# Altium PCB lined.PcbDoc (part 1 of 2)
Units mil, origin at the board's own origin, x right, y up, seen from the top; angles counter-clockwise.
Board outline 3500.17 x 4287.12 mil, 2 copper layers (Top Layer, Bottom Layer); 109 components, 117 nets, 494 pads, 325 vias.
Unrouted connection lines stored in the file: 3.
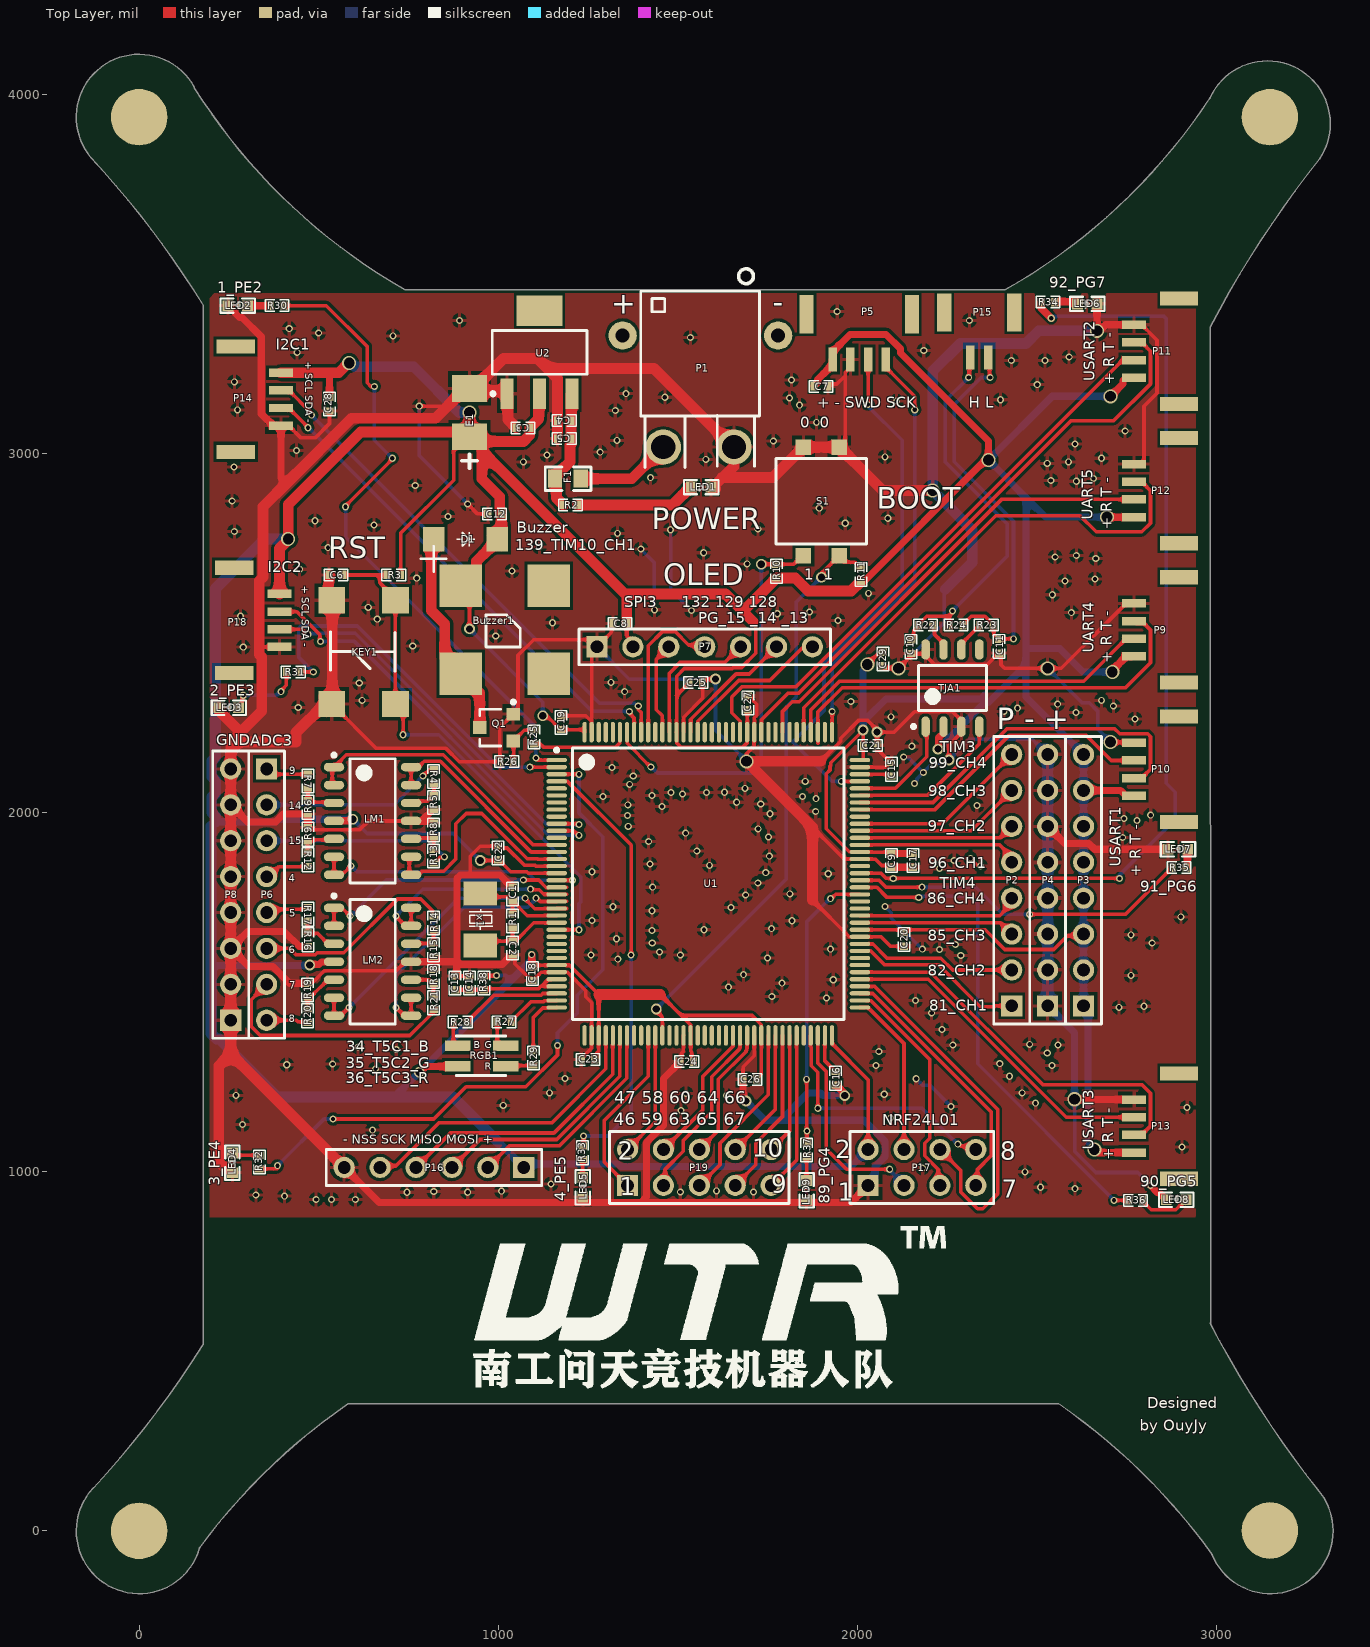
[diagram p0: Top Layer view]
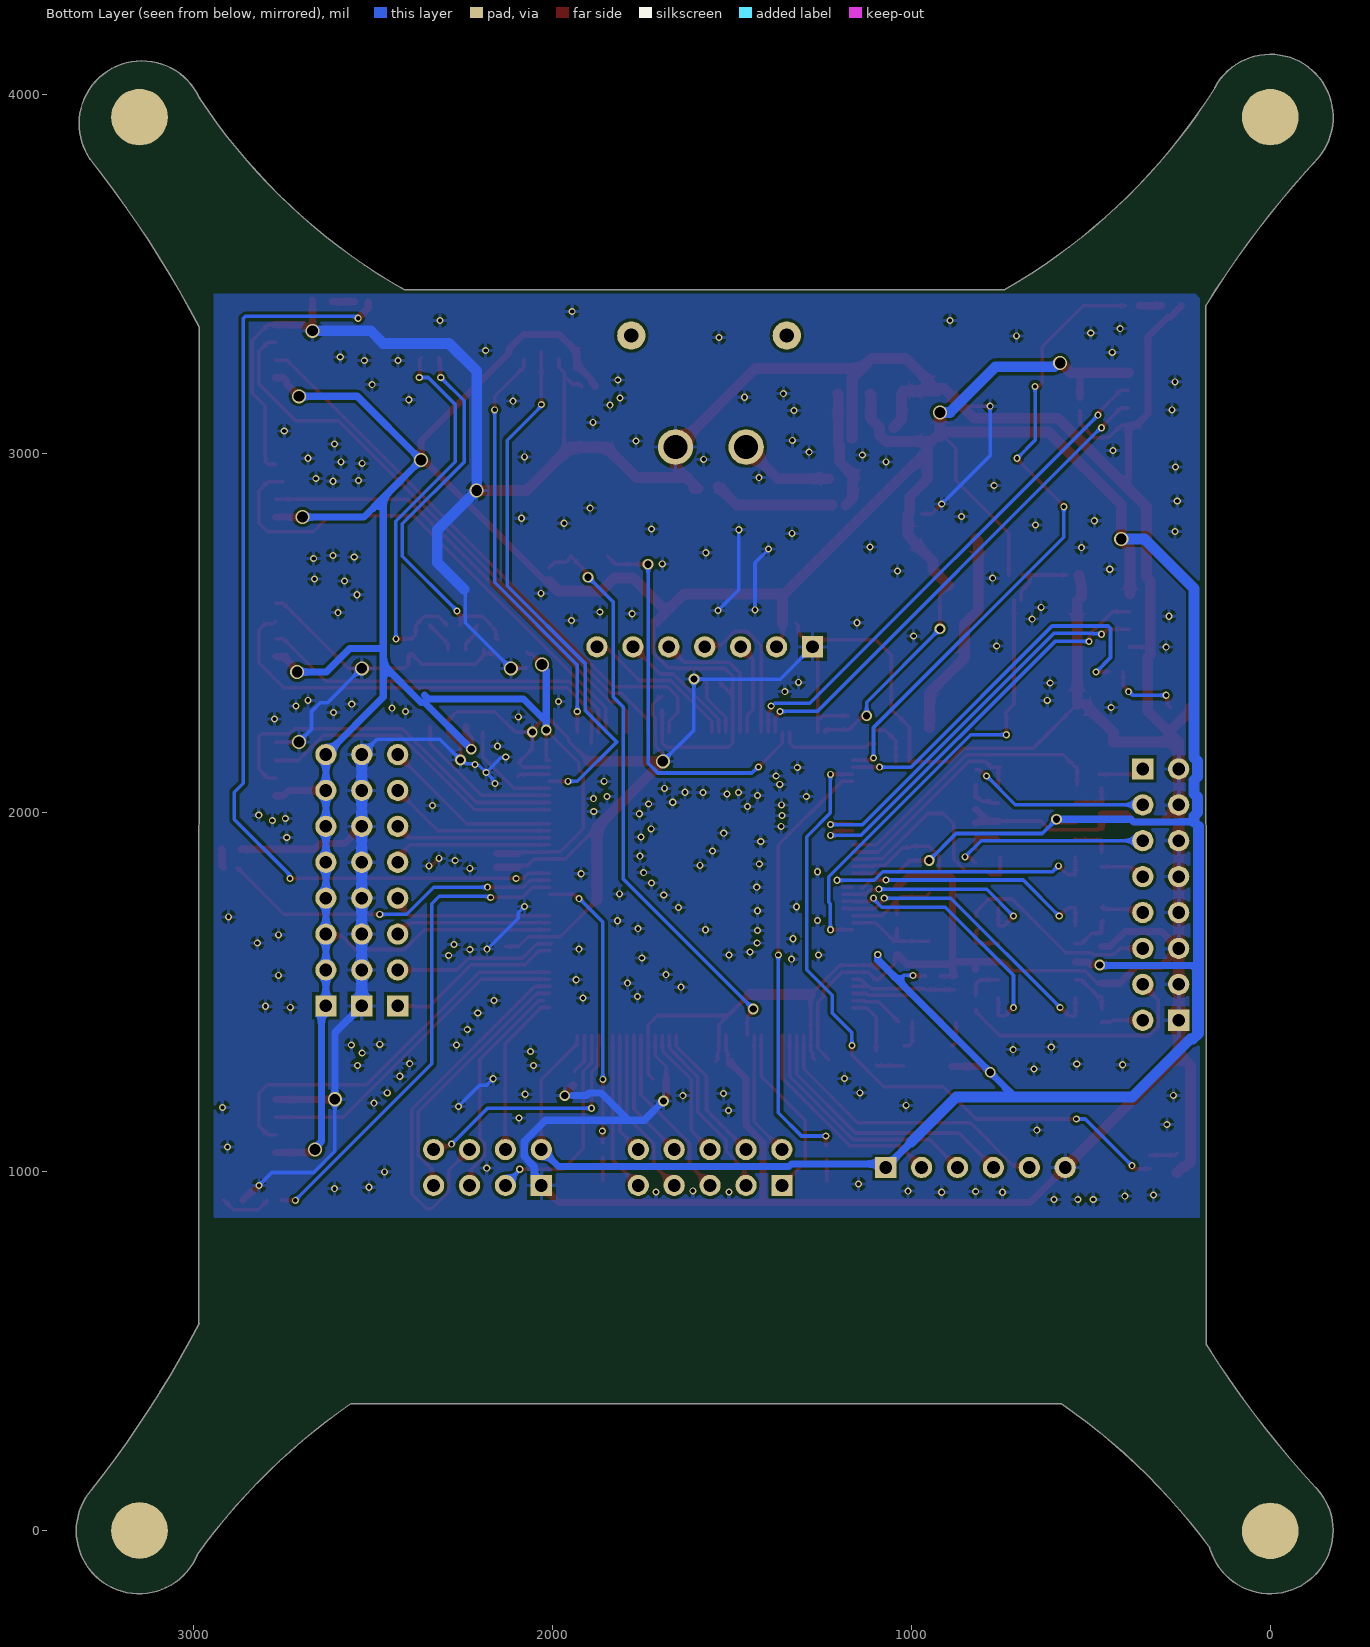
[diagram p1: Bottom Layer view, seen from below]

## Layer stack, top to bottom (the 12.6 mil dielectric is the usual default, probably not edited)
Top Solder: solder mask 0.4, Solder Resist, Dk 3.5
Top Layer: signal copper 1.4
Dielectric 1: dielectric 12.6, FR-4, Dk 4.8
Bottom Layer: signal copper 1.4
Bottom Solder: solder mask 0.4, Solder Resist, Dk 3.5

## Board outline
167.93,-49.57 ccw(c163.12,-48.15) 168.13,-48.15 ccw(c163.12,-48.15) 168.05,-47.24 cw(c1570.21,-1079.6) 581.36,353.58 ccw(c578.51,357.71) 581.98,354.09 ccw(c583,359) 583,353.98 2557.27,353.98 ccw(c2557.27,359) 2559.71,354.62 cw(c1564,-1088) 2987.16,-64.67 ccw(c2991.23,-61.74) 2987.79,-65.39 ccw(c2992.78,-64.85) 2988.14,-66.77 ccw(c3150,0) 3325.09,0 ccw(c3150,0) 3282.24,114.75 ccw(c3278.45,111.47) 3282.04,114.97 ccw(c3278,112) 3281.94,115.1 cw(c5634.72,1965.17) 2982.72,577.64 ccw(c2979,581) 2984.02,581 ccw(c2979,581) 2984.02,581 2982.38,3352.51 cw(c5629.85,1961.54) 3286.87,3820.13 ccw(c3282.94,3823.25) 3287.68,3821.59 ccw(c3284,3825) 3288.18,3822.23 ccw(c3142.11,3918.77) 3317.2,3918.77 ccw(c3142.11,3918.77) 2982.26,3990.2 ccw(c2985,3986) 2980.81,3988.76 cw(c1584.9,4910.46) 2411,3455.93 ccw(c2410.1,3451) 2410.1,3456.02 740.86,3456.02 ccw(c737.85,3452.01) 740.34,3456.36 cw(c1571.31,4910.32) 153.91,4018.42 ccw(c148.94,4019.11) 153.96,4019.11 ccw(c148.94,4019.11) 153.33,4021.53 ccw(c0,3937) -133.4,3823.6 ccw(c-129,3826) -132.69,3822.6 cw(c-2129,1980.08) 179.16,3412.76 177.98,520 ccw(c183,520) 178.16,518.68 ccw(c181.15,514.65) 176.9,517.32 cw(c-2129,1966) -127.15,119.8 ccw(c-125.1,115.22) -128.79,118.62 ccw(c0,0)

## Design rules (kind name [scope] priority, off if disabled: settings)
Clearance [All] p1: gap=8 ignorepadtopadclearanceinfootprint=TRUE except(0: Arc-Hole Track-Hole SMDPad-Hole THPad-Hole Via-Hole Fill-Hole Poly-Hole Region-Hole Text-Hole)
ComponentClearance [All] p1: gap=0 collisioncheckmode=3 verticalgap=0 showdistances=FALSE
MinimumSolderMaskSliver [All] p1: minsoldermaskwidth=0
PolygonConnect [All] p1: connectstyle=Relief reliefconductorwidth=10 reliefentries=4 polygonreliefangle="90 Angle" airgapwidth=10
RoutingVias [All] p1: holewidth=11.81 width=19.68 viastyle="Through Hole" minholewidth=11.81 minwidth=11.81 maxholewidth=39.37 maxwidth=39.37
SilkToSilkClearance [All] p1: silktosilkclearance=0
SilkToSolderMaskClearance [IsPad] p1: minsilkscreentomaskgap=0 clearancetoexposedcopper=TRUE
SolderMaskExpansion [All] p1: expansion=4
Width [All] p1: maxlimit=100 minlimit=5 preferedwidth=10
26 further rules are at their usual default settings.

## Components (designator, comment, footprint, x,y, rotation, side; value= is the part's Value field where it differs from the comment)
Buzzer1 "Buzzer" BUZZER 1185.3,2677 r180 top
C1 "22PF" 0402 1040,1773.5 r90 top
C2 "22PF" 0402 1040,1623.5 r270 top
C3 "0.1uf" 0402 1069,3072 r180 top
C4 "0.1uf" 0402 1184,3092 r180 top
C5 "10uf" 0402 1184,3042 r180 top
C6 "1uf" 0402 548,2662 r180 top
C7 "0.1uf" 0402 1899,3187 r180 top
C8 "0.1uf" 0402 1339,2527 r0 top
C9 "0.1uf" 0402 2095,1867 r270 top
C10 "30pf" 0402 2150,2462.4 r90 top
C11 "30pf" 0402 2395,2463.2 r90 top
C12 "10uf" 0402 990,2832.06 r0 top
C13 "10uf" 0402 880,1526 r270 top
C14 "104" 0402 920,1526 r270 top
C15 "225" 0402 2095,2121 r270 top
C16 "225" 0402 1939.77,1260.28 r90 top
C17 "106" 0402 2155,1867 r90 top
C18 "104" 0402 1095,1552 r90 top
C19 "104" 0402 1175,2251 r270 top
C20 "104" 0402 2130,1647 r90 top
C21 "104" 0402 2036,2187 r180 top
C22 "104" 0402 1000,1887.9 r270 top
C23 "104" 0402 1250,1312.7 r0 top
C24 "104" 0402 1525,1307 r0 top
C25 "104" 0402 1550,2362.24 r180 top
C26 "104" 0402 1701,1257.58 r0 top
C27 "104" 0402 1695,2305.61 r270 top
C28 "104" 0402 530,3138 r90 top
C29 "104" 0402 2070.89,2428 r90 top
D1 "DIODE" DIODE 997.17,2762 r180 top
E1 "100uF/10V" 3528 920,3047 r90 top
F1 "Fuse" 0805 1193.85,2930.15 r0 top
KEY1 "Key" 6*6*5轻触开关 625,2447 r90 top
LED1 "green" 0603 1565,2907 r0 top
LED2 "red" 0603 275,3412 r180 top
LED3 "red" 0603 250,2292 r180 top
LED4 "red" 0603 260,1025 r270 top
LED5 "red" 0603 1235.67,957 r270 top
LED6 "green" 0603 2640,3417 r0 top
LED7 "green" 0603 2893,1898.06 r180 top
LED8 "green" 0603 2887.98,922 r180 top
LED9 "green" 0603 1858.74,948.48 r270 top
LM1 "LM324" LM324 650,1977 r0 top
LM2 "LM324" LM324 650,1584.81 r0 top
P1 "Header 2" XT30-PW-M 1558,3215 r0 top
P2 "Header 8" HDR1X8 2430,1462 r90 top
P3 "Header 8" HDR1X8 2630,1462 r90 top
P4 "Header 8" HDR1X8 2530,1462 r90 top
P5 "Header 4" GH1.25_4P 2005.39,3341.72 r180 top
P6 "Header 8" HDR1X8 355,2122 r270 top
P7 "Header 7" HDR1X7 1275,2462 r0 top
P8 "Header 8" HDR1X8 255,1422 r90 top
P9 "Header 4" GH1.25_4P 2849.72,2508.89 r90 top
P10 "Header 4" GH1.25_4P 2849.72,2120.82 r90 top
P11 "Header 4" GH1.25_4P 2849.72,3285.03 r90 top
P12 "Header 4" GH1.25_4P 2849.72,2896.96 r90 top
P13 "Header 4" GH1.25_4P 2849.72,1127.39 r90 top
P14 "Header 4" GH1.25_4P 315.28,3151.61 r270 top
P15 "Header 2" GH1.25_2P 2437.05,3504.98 r180 top
P16 "Header 6" HDR1X6 1071,1012 r180 top
P17 "Header 4X2" HDR2X4 2030,962 r0 top
P18 "Header 4" GH1.25_4P 311.26,2535.35 r270 top
P19 "Header 5X2" HDR2X5 1360,962 r0 top
Q1 "S8050" SOT-23R 1000,2237 r90 top
R1 "1M" 0402 1040.13,1698.5 r90 top
R2 "560R" 0402 1201,2857 r0 top
R3 "10K" 0402 709,2662 r0 top
R4 "100K" 0402 820,2101 r270 top
R5 "100K" 0402 820,2028.06 r90 top
R6 "100K" 0402 469.97,2015 r90 top
R7 "100K" 0402 469.97,2088 r90 top
R8 "100K" 0402 820,1951.87 r270 top
R9 "100K" 0402 469.97,1940 r270 top
R10 "10K" 0402 1774.8,2672.64 r270 top
R11 "10K" 0402 2009.8,2663.64 r90 top
R12 "100K" 0402 469.97,1868.9 r270 top
R13 "100K" 0402 820,1879.06 r270 top
R14 "100K" 0402 820,1693 r270 top
R15 "100K" 0402 820,1618.16 r90 top
R16 "100K" 0402 469.97,1646 r90 top
R17 "100K" 0402 469.97,1717.19 r90 top
R18 "100K" 0402 820,1544.16 r270 top
R19 "100K" 0402 469.23,1506.16 r270 top
R20 "100K" 0402 469.23,1434.35 r270 top
R21 "100K" 0402 820,1471 r270 top
R22 "0R" 0402 2190,2522.2 r180 top
R23 "0R" 0402 2359,2522.2 r0 top
R24 "120R" 0402 2275,2522.2 r180 top
R25 "510R" 0402 1100,2211 r90 top
R26 "10K" 0402 1023.7,2142 r0 top
R27 "47R" 0402 1016.17,1417.55 r180 top
R28 "47R" 0402 894,1417 r0 top
R29 "68R" 0402 1097.58,1317 r270 top
R30 "1K" 0402 384,3412 r0 top
R31 "1K" 0402 429,2392 r0 top
R32 "1K" 0402 335,1027 r270 top
R33 "1K" 0402 1235,1053 r90 top
R34 "510R" 0402 2531,3422 r180 top
R35 "510R" 0402 2895.98,1847 r180 top
R36 "510R" 0402 2775,920.5 r180 top
R37 "510R" 0402 1858.68,1060.62 r90 top
R38 "10R" 0402 960,1526 r270 top
RGB1 "RGB" RGB_LED 954.14,1322 r0 top
S1 "Switch" SWITCH_2P 1899.8,2867.11 r0 top
TJA1 "TJA1050" TJA1050 2265,2347.2 r90 top
U1 "STM32F407ZGT6" STM32F103ZETx 1585,1802 r0 top
U2 "AMS1117-3.3" ASM1117 1115,3282 r90 top
x1 "8MHz" 8M晶振 950,1702.5 r270 top

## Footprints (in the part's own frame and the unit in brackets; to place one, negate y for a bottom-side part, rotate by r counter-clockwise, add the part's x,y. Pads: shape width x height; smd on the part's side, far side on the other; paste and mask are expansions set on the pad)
6*6*5轻触开关 [mm]
  rect 1.85x1.9 smd: 1(-3.675,2.25) 2(3.675,2.25) 3(-3.675,-2.25) 4(3.675,-2.25)
  silkscreen extent -1.35,-2.22 1.45,2.35
8M晶振 [mm]
  rect 1.7x2.4 smd: 1(-1.85,0) 2(1.85,0)
  silkscreen extent -0.72,-0.77 0.72,0.87, body extent -2.5,-1.6 2.5,1.6, height 0.25
0402 [mil]
  rect 20x23.62 smd: 1(-19,0) 2(19,0)
  silkscreen extent -33,-16 33,16
0603 [mil]
  rect 30x30 smd: 1(-27,0) 2(27.5,-0.06)
  silkscreen extent -48,-20 48,20
0805 [mil]
  rect 39.37x50 smd: 1(-36,0) 2(36,0)
  silkscreen extent -63,-33 64,33
3528 [mm]
  rect 1.9x2.5 smd: 1(0,0) 2(3.42,0)
  silkscreen extent -2.24,-0.56 -1.24,0.56
ASM1117 [mm] "SOT223, 4-Leads, Body 6.51x7.00mm (avg), Pitch 2.30mm, IPC Medium Density"
  rect 2.15x0.9 smd: 1(-2.93,2.3) 2(-2.93,0) 3(-2.93,-2.3)
  rect 2.15x3.25 smd: 4(2.93,0)
  silkscreen extent -3.05,-3.35 1.55,3.42, body extent -1.86,-3.35 1.86,3.35, height 1.8
BUZZER [mil]
  rect 118.11x118.11 smd: 1(290,45) 2(290,290) 3(45,290) 4(45,45)
  silkscreen extent 124,-65 400,216
DIODE [mm] "SODFL, 2-Leads, Body 3.63x5.35mm, IPC Medium Density"
  rect 1.52x1.724 smd: 1(0,0) 2(4.5,0)
  silkscreen extent 1.57,-0.5 2.86,0.52
GH1.25_2P [mm]
  rect 1x2.7 smd: 0(0,2.845) 0(4.95,2.845)
  rect 0.6x1.7 smd: 1(1.85,6.045) 2(3.1,6.045)
GH1.25_4P [mm]
  rect 1x2.7 smd: 0(-3.725,-1.175) 0(3.725,-1.175)
  rect 0.6x1.7 smd: 1(-1.875,2.025) 2(-0.625,2.025) 3(0.625,2.025) 4(1.875,2.025)
HDR1X6 [mm] "Connector; Header; 6 Position"
  rect 1.5x1.5 hole 0.9: 1(0,0)
  round 1.5 hole 0.9: 2(2.54,0) 3(5.08,0) 4(7.62,0) 5(10.16,0) 6(12.7,0)
  silkscreen extent -1.27,-1.27 13.97,1.27
HDR1X7 [mm] "Connector; Header; 7 Position"
  rect 1.5x1.5 hole 0.9: 1(0,0)
  round 1.5 hole 0.9: 2(2.54,0) 3(5.08,0) 4(7.62,0) 5(10.16,0) 6(12.7,0) 7(15.24,0)
  silkscreen extent -1.27,-1.27 16.51,1.27
HDR1X8 [mm] "Connector; Header; 8 Position"
  rect 1.5x1.5 hole 0.9: 1(0,0)
  round 1.5 hole 0.9: 2(2.54,0) 3(5.08,0) 4(7.62,0) 5(10.16,0) 6(12.7,0) 7(15.24,0) 8(17.78,0)
  silkscreen extent -1.27,-1.27 19.05,1.27
HDR2X4 [mm] "Connector; Header; 4x2 Position"
  rect 1.5x1.5 hole 0.9: 1(0,0)
  round 1.5 hole 0.9: 2(0,2.54) 3(2.54,0) 4(2.54,2.54) 5(5.08,0) 6(5.08,2.54) 7(7.62,0) 8(7.62,2.54)
  silkscreen extent -1.27,-1.27 8.89,3.81
HDR2X5 [mm] "Connector; Header; 5x2 Position"
  rect 1.5x1.5 hole 0.9: 1(0,0)
  round 1.5 hole 0.9: 2(0,2.54) 3(2.54,0) 4(2.54,2.54) 5(5.08,0) 6(5.08,2.54) 7(7.62,0) 8(7.62,2.54) 9(10.16,0) 10(10.16,2.54)
  silkscreen extent -1.27,-1.27 11.43,3.81
LM324 [mm] "SOIC, 14-Leads, Body 8.65x3.90mm, Pitch 1.27mm, IPC Medium Density"
  oval 1.45x0.6 smd: 1(-2.725,3.81) 2(-2.725,2.54) 3(-2.725,1.27) 4(-2.725,0) 5(-2.725,-1.27) 6(-2.725,-2.54) 7(-2.725,-3.81) 8(2.725,-3.81) 9(2.725,-2.54) 10(2.725,-1.27) 11(2.725,0) 12(2.725,1.27) 13(2.725,2.54) 14(2.725,3.81)
  silkscreen extent -2.85,-4.4 1.6,4.78, body extent -2,-4.4 2,4.4, height 1.75
RGB_LED [mm]
  rect 1.8x0.75 smd: 1(-1.7,-0.725) 2(-1.7,0.725) 3(1.7,-0.725) 4(1.7,0.725)
  silkscreen extent -1.8,-1.36 1.7,1.44
SOT-23R [mm] "SOT-23; 3 Leads; Body 3.0 x 2.5 mm, inc. leads (LxW max)"
  rect 0.9x0.95 smd: 1(0.95,-1.048) 2(-0.95,-1.048) 3(0,1.302)
  silkscreen extent -1.3,-1.19 1.93,1.3
STM32F103ZETx [mm] "TSQFP, 144-Leads, Body 20.00x20.00mm, Pitch 0.50mm, IPC Medium Density"
  oval 1.45x0.3 smd: 1(-10.725,8.75) 2(-10.725,8.25) 3(-10.725,7.75) 4(-10.725,7.25) 5(-10.725,6.75) 6(-10.725,6.25) 7(-10.725,5.75) 8(-10.725,5.25) 9(-10.725,4.75) 10(-10.725,4.25) 11(-10.725,3.75) 12(-10.725,3.25) 13(-10.725,2.75) 14(-10.725,2.25) 15(-10.725,1.75) 16(-10.725,1.25) 17(-10.725,0.75) 18(-10.725,0.25) 19(-10.725,-0.25) 20(-10.725,-0.75) 21(-10.725,-1.25) 22(-10.725,-1.75) 23(-10.725,-2.25) 24(-10.725,-2.75) 25(-10.725,-3.25) 26(-10.725,-3.75) 27(-10.725,-4.25) 28(-10.725,-4.75) 29(-10.725,-5.25) 30(-10.725,-5.75) 31(-10.725,-6.25) 32(-10.725,-6.75) 33(-10.725,-7.25) 34(-10.725,-7.75) 35(-10.725,-8.25) 36(-10.725,-8.75) 73(10.725,-8.75) 74(10.725,-8.25) 75(10.725,-7.75) 76(10.725,-7.25) 77(10.725,-6.75) 78(10.725,-6.25) 79(10.725,-5.75) 80(10.725,-5.25) 81(10.725,-4.75) 82(10.725,-4.25) 83(10.725,-3.75) 84(10.725,-3.25) 85(10.725,-2.75) 86(10.725,-2.25) 87(10.725,-1.75) 88(10.725,-1.25) 89(10.725,-0.75) 90(10.725,-0.25) 91(10.725,0.25) 92(10.725,0.75) 93(10.725,1.25) 94(10.725,1.75) 95(10.725,2.25) 96(10.725,2.75) 97(10.725,3.25) 98(10.725,3.75) 99(10.725,4.25) 100(10.725,4.75) 101(10.725,5.25) 102(10.725,5.75) 103(10.725,6.25) 104(10.725,6.75) 105(10.725,7.25) 106(10.725,7.75) 107(10.725,8.25) 108(10.725,8.75)
  oval 0.3x1.45 smd: 37(-8.75,-10.725) 38(-8.25,-10.725) 39(-7.75,-10.725) 40(-7.25,-10.725) 41(-6.75,-10.725) 42(-6.25,-10.725) 43(-5.75,-10.725) 44(-5.25,-10.725) 45(-4.75,-10.725) 46(-4.25,-10.725) 47(-3.75,-10.725) 48(-3.25,-10.725) 49(-2.75,-10.725) 50(-2.25,-10.725) 51(-1.75,-10.725) 52(-1.25,-10.725) 53(-0.75,-10.725) 54(-0.25,-10.725) 55(0.25,-10.725) 56(0.75,-10.725) 57(1.25,-10.725) 58(1.75,-10.725) 59(2.25,-10.725) 60(2.75,-10.725) 61(3.25,-10.725) 62(3.75,-10.725) 63(4.25,-10.725) 64(4.75,-10.725) 65(5.25,-10.725) 66(5.75,-10.725) 67(6.25,-10.725) 68(6.75,-10.725) 69(7.25,-10.725) 70(7.75,-10.725) 71(8.25,-10.725) 72(8.75,-10.725) 109(8.75,10.725) 110(8.25,10.725) 111(7.75,10.725) 112(7.25,10.725) 113(6.75,10.725) 114(6.25,10.725) 115(5.75,10.725) 116(5.25,10.725) 117(4.75,10.725) 118(4.25,10.725) 119(3.75,10.725) 120(3.25,10.725) 121(2.75,10.725) 122(2.25,10.725) 123(1.75,10.725) 124(1.25,10.725) 125(0.75,10.725) 126(0.25,10.725) 127(-0.25,10.725) 128(-0.75,10.725) 129(-1.25,10.725) 130(-1.75,10.725) 131(-2.25,10.725) 132(-2.75,10.725) 133(-3.25,10.725) 134(-3.75,10.725) 135(-4.25,10.725) 136(-4.75,10.725) 137(-5.25,10.725) 138(-5.75,10.725) 139(-6.25,10.725) 140(-6.75,10.725) 141(-7.25,10.725) 142(-7.75,10.725) 143(-8.25,10.725) 144(-8.75,10.725)
  silkscreen extent -10.85,-9.6 9.6,9.6, body extent -10,-10 10,10, height 1.6
SWITCH_2P [mm]
  rect 1.1x1.1 smd: 1(-1.27,3.835) 2(-1.27,-3.835) 3(1.27,3.835) 4(1.27,-3.835)
  silkscreen extent -3.2,-3.03 3.2,3.03
TJA1050 [mm] "SOIC, 8-Leads, Body 4.90x3.90mm, Pitch 1.27mm, IPC Medium Density"
  oval 1.45x0.6 smd: 1(-2.725,1.905) 2(-2.725,0.635) 3(-2.725,-0.635) 4(-2.725,-1.905) 5(2.725,-1.905) 6(2.725,-0.635) 7(2.725,0.635) 8(2.725,1.905)
  silkscreen extent -2.85,-2.4 1.6,2.88, body extent -2,-2.4 2,2.4, height 1.75
XT30-PW-M [mm]
  round 2 hole 1: 0(-5.375,2.892) 0(5.625,2.892)
  round 2.5 hole 1.7: 1(-2.5,-5) 2(2.5,-5)
  silkscreen extent -4.09,-6.45 4.32,7.61

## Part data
C1 C2 C3 C4 C5 C6 C7 C8 C9 C10 C11 C12 C13 C14 C15 C16 C17 C18 C19 C20 C21 C22 C23 C24 C25 C26 C27 C28 C29: library part C
E1: library part C-CM, "钽电容"
LED1 LED2 LED3 LED4 LED5 LED6 LED7 LED8 LED9: library part LED
P1 P15: "Header, 2-Pin"
P2 P3 P4 P6 P8: "Header, 8-Pin"
P5 P9 P10 P11 P12 P13 P14 P18: "Header, 4-Pin"
P7: "Header, 7-Pin"
P16: "Header, 6-Pin"
P17: "Header, 4-Pin, Dual row"
P19: "Header, 5-Pin, Dual row"
Q1: library part NPN, "8050/BCW846/BCW847"
R1 R2 R3 R4 R5 R6 R7 R8 R9 R10 R11 R12 R13 R14 R15 R16 R17 R18 R19 R20 R21 R22 R23 R24 R25 R26 R27 R28 R29 R30 R31 R32 R33 R34 R35 R36 R37 R38: library part R
x1: library part XTAL_8MHz

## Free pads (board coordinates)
  round 157.48 all layers, no hole: 2(0,0) 2(0,3937) 2(3149,1) 2(3149,3937)

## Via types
v1: diameter 19.68, hole 11.81, Top Layer to Bottom Layer, tented both sides, 293 vias
v2: diameter 30, hole 20, Top Layer to Bottom Layer, tented both sides, 16 vias
v3: diameter 39, hole 30, Top Layer to Bottom Layer, tented both sides, 16 vias

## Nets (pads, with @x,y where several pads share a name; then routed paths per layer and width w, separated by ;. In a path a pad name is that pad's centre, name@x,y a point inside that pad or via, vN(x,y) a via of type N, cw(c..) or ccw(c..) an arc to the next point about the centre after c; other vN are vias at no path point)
ADC3_4: LM1.6 LM1.7 U1.18 | length 800.9
  Top Layer w10: LM1.6@542.72,1877 LM1.7@542.72,1828.14 ; LM1.7@558.31,1828.14 LM1.7@542.72,1828.14 ; v1(590,1852) 572.43,1834.43 570.57,1834.43 563.13,1827 LM1.7@542.72,1827 LM1.7@542.72,1828.14 ; U1.18@1162.76,1811.84 1162.83,1811.92 v1(1206.92,1811.92)
  Bottom Layer w10: v1(590,1852) 606.5,1835.5 1079.46,1835.5 1103.04,1811.92 v1(1206.92,1811.92)
ADC3_5: LM2.1 LM2.2 U1.19 | length 734.3
  Top Layer w10: LM2.2@542.72,1684.81 LM2.1@542.72,1734.81 563.13,1734.81 568.38,1729.57 570.07,1729.57 v1(587.63,1712) ; v1(1070,1812.66) 1112.42,1812.66 1133.7,1791.38 U1.19@1139.65,1791.38 ; U1.19@1162.76,1792.16 1162.76,1792.32 U1.19@1190,1792.32
  Bottom Layer w10: v1(587.63,1712) 688.3,1812.66 v1(1070,1812.66)
ADC3_6: LM2.13 LM2.14 U1.20 | length 616.1
  Top Layer w10: v1(715,1712) 715,1711.18 741.37,1684.81 LM2.13@757.28,1684.81 LM2.14@757.28,1734.81 ; v1(1090,1787) 1091.85,1785.15 1114.47,1785.15 1126.8,1772.82 1162.41,1772.82 U1.20@1162.76,1772.47 ; U1.20@1162.76,1772.63 U1.20@1190,1772.63
  Bottom Layer w10: v1(715,1712) 790,1787 v1(1090,1787)
ADC3_7: LM2.8 LM2.9 U1.21 | length 761.2
  Top Layer w10: v1(715,1457) 716.68,1457 738.87,1434.81 LM2.8@757.28,1434.81 LM2.9@757.28,1484.81 ; v1(1105,1762) 1107.62,1762 1116.83,1752.79 U1.21@1162.76,1752.79 U1.21@1162.41,1753.13 ; U1.21@1162.76,1752.94 U1.21@1190,1752.94
  Bottom Layer w10: v1(715,1457) 715,1547 905,1737 1082.3,1737 1105,1759.7 v1(1105,1762)
ADC3_8: LM2.6 LM2.7 U1.22 | length 846.8
  Top Layer w10: LM2.6@542.72,1484.81 LM2.7@542.72,1434.81 560.87,1434.81 583.57,1457.51 v1(585,1457.51) ; v1(1075,1762) 1075,1759.38 1101.62,1732.76 1162.41,1732.76 U1.22@1162.76,1733.1 1162.76,1733.26 U1.22@1190,1733.26
  Bottom Layer w10: v1(585,1457.51) 889.49,1762 v1(1075,1762)
ADC3_9: LM1.1 LM1.2 U1.13 | length 824.7
  Top Layer w10: LM1.2@537.72,2077 537.72,2127 LM1.1@542.72,2127 576.72,2161 846.85,2161 1097.58,1910.27 1131.16,1910.27 U1.13@1162.76,1910.27 1162.41,1910.61 1131.16,1910.61
ADC3_14: LM1.13 LM1.14 U1.14 | length 573.7
  Top Layer w10: LM1.13@757.28,2077 757.28,2122 752.28,2127 LM1.14@757.28,2127 777.7,2127 793.7,2143 839,2143 1091.42,1890.58 U1.14@1162.76,1890.58
ADC3_15: LM1.8 LM1.9 U1.15 | length 641.2
  Top Layer w10: LM1.9@752.28,1877 752.28,1827 LM1.8@757.28,1827 777.7,1827 787.7,1837 848,1837 881.9,1870.9 881.9,1968.9 910.86,1997.86 954.14,1997.86 1032.1,1919.9 1080.5,1871.5 1109.76,1871.5 1110.37,1870.9 U1.15@1162.76,1870.9
ADC_CH1: P6.1 R7.2 | length 129.2
  Top Layer w10: P6.1@355,2122 370,2107 R7.2@469.97,2107 R7.2@478,2107
ADC_CH2: P6.2 R4.1 | length 507.4
  Top Layer w10: v1(790,2102) 807.57,2119.57 819.57,2119.57 R4.1@820,2120 ; R4.1@815.03,2120 R4.1@816.84,2120
  Bottom Layer w10: P6.2@355,2022 710,2022 v1(790,2102)
ADC_CH3: P6.3 R13.2 | length 550.7
  Top Layer w10: R13.2@820,1860.06 821.81,1860.06 836.89,1875.15 848.15,1875.15 v1(850,1877)
  Bottom Layer w10: P6.3@355,1922 805,1922 v1(850,1877)
ADC_CH4: P6.4 R12.2 | length 126.5
  Top Layer w10: P6.4@355,1822 362.18,1822 390.07,1849.9 R12.2@469.97,1849.9
ADC_CH5: P6.5 R17.2 | length 129.7
  Top Layer w10: P6.5@355,1722 364.19,1731.19 464.97,1731.19 R17.2@469.97,1736.19 R17.2@464.97,1741.19 ; R17.2@465,1736.19 R17.2@466.81,1736.19
ADC_CH6: P6.6 R14.1 | length 564.7
  Top Layer w10: P6.6@355,1622 418.72,1622 436.72,1604 490.78,1604 496.78,1610 569.73,1610 719.35,1759.62 784.29,1759.62 818.19,1725.73 818.19,1712 R14.1@820,1712
ADC_CH7: P6.7 R21.2 | length 694.3
  Top Layer w10: P6.7@355,1522 312.47,1479.47 312.47,1404.38 337.38,1379.47 753.77,1379.47 820,1445.71 R21.2@820,1448.38 ; R21.2@818.19,1447 819.57,1448.38 R21.2@820,1448.38 ; R21.2@820,1448.38 818.19,1450.19 R21.2@820,1452 R21.2@820,1448.38
ADC_CH8: P6.8 R20.2 | length 118.8
  Top Layer w10: P6.8@355,1422 437.97,1422 442.42,1417.55 467.04,1417.55 R20.2@469.23,1415.35 R20.2@467.42,1415.35
BOOT0: R10.1 S1.2 U1.138 | length 1125.9
  Top Layer w10: U1.138@1358.62,2224.24 1358.97,2223.9 1358.97,2193.03 v1(1425,2127) ; v2(1732.64,2692) 1822.85,2692 S1.2@1844.8,2713.96
  Bottom Layer w10: v1(1425,2127) 1427.13,2127 1443.63,2110.5 1705.12,2110.5 1732.47,2137.85 1732.47,2691.83 v2(1732.64,2692)
BOOT1: R11.2 S1.4 U1.48 | length 1633.9
  Top Layer w10: v2(1440,1453.35) 1440,1447.93 1457.05,1430.89 U1.48@1457.05,1379.76 ; v2(1900,2655.65) 1900,2666.32 S1.4@1946.22,2712.54 ; S1.4@1944.8,2713.96 S1.4@1946.22,2712.54 ; S1.4@1949.8,2716.12 S1.4@1946.22,2712.54 ; R11.2@2009.8,2682.64 2007.99,2682.64 1993.33,2697.3 1961.46,2697.3 S1.4@1946.22,2712.54
  Bottom Layer w10: v2(1440,1453.35) 1802,1815.35 1802,2294.46 1830,2322.46 1830,2587 v2@1900,2657
Buzzer: R25.1 U1.139 | length 277.4
  Top Layer w10: R25.1@1100,2192 1116.83,2192 1126.13,2182.7 1327.08,2182.7 1338.59,2194.21 1338.59,2223.9 U1.139@1338.94,2224.24
CAN_RX: TJA1.4 U1.103 | length 440.1
  Top Layer w10: U1.103@2007.24,2048.06 2195.66,2048.06 2340,2192.4 TJA1.4@2340,2239.92
CAN_TX: TJA1.1 U1.104 | length 291.9
  Top Layer w10: U1.104@2007.24,2067.75 2007.59,2068.09 2106.09,2068.09 2193.62,2155.62 TJA1.1@2193.62,2224.72
CANH: C10.2 P15.2 R22.2 R24.2 | length 1080.3
  Top Layer w10: C10.2@2150,2481.4 2151.81,2481.4 2156.81,2486.4 2156.81,2506.2 2171,2520.39 R22.2@2171,2522.2 2171,2524.01 2183.71,2536.72 2183.71,2537.1 2193.62,2547.01 2254.99,2547.01 ; R24.2@2256,2522.2 2254.99,2523.21 2254.99,2547.01 ; v1(2265,2562) 2265,2557.02 2254.99,2547.01 ; v1(2310,3212) 2311.85,3213.85 2311.85,3263.85 P15.2@2315,3267 P15.2@2315,3245.35
  Bottom Layer w10: v1(2265,2562) 2417,2714 2417,2804.54 2245,2976.54 2245,3147 v1(2310,3212)
CANL: C11.2 P15.1 R23.2 R24.1 | length 1105.4
  Top Layer w10: R24.1@2294,2522.2 2294,2524.01 2317,2547.01 2355.38,2547.01 2363,2539.4 2363,2539.01 2378,2524.01 R23.2@2378,2522.2 2380,2520.2 2380,2495.39 2393.19,2482.2 2395.27,2484.28 v1(2435,2484.28) ; P15.1@2364.21,3267 2368.15,3263.07 2368.15,3213.85 v1(2370,3212)
  Bottom Layer w10: v1(2370,3212) 2345,3212 2270,3137 2270,2977 2435,2812 v1(2435,2484.28)
CE: P17.3 U1.70 | length 586.7
  Top Layer w10: U1.70@1890.12,1379.76 1890.12,1302.8 1912.96,1279.96 1912.96,1064.04 1970,1007 v1(2090,1007)
  Bottom Layer w10: v1@2088.75,1005.75 2130,964.5 P17.3@2130,962
CS: P7.7 U1.128 | length 435.4
  Top Layer w10: U1.128@1555.47,2224.24 1555.82,2224.59 1555.82,2254.28 1669.74,2368.2 1756.2,2368.2 1845.33,2457.33 1870.33,2457.33 P7.7@1875,2462
CSN: P17.4 U1.73 | length 459.6
  Top Layer w10: U1.73@2007.24,1457.51 2029.88,1457.51 2130,1357.39 P17.4@2130,1062
DC: P7.6 U1.129 | length 358.5
  Top Layer w10: U1.129@1535.79,2224.24 1536.13,2224.59 1536.13,2260.05 1662.28,2386.2 1699.2,2386.2 P7.6@1775,2462
EXIT_0: P19.1 U1.46 | length 495.5
  Top Layer w10: P19.1@1360,962 1295,1027 1295,1142.98 1417.68,1265.65 U1.46@1417.68,1379.76
EXIT_1: P19.2 U1.47 | length 349.8
  Top Layer w10: P19.2@1360,1062 1437.36,1139.36 U1.47@1437.36,1379.76
EXIT_7: P19.4 U1.58 | length 398.1
  Top Layer w10: P19.4@1460,1062 1570,1172 1570,1265.65 1653.9,1349.55 U1.58@1653.9,1379.76
EXIT_8: P19.3 U1.59 | length 506.2
  Top Layer w10: P19.3@1460,962 1464.67,966.67 1464.67,1006.53 1515,1056.86 1515,1087 1594.84,1166.84 1594.84,1265.04 1671.9,1342.09 1671.9,1344.06 1673.58,1345.74 U1.59@1673.58,1379.76
EXIT_9: P19.6 U1.60 | length 373.4
  Top Layer w10: P19.6@1560,1062 1612.84,1114.84 1612.84,1257.58 1689.9,1334.64 1689.9,1336.6 1691.58,1338.28 1691.58,1341.86 1693.27,1343.54 U1.60@1693.27,1379.76 U1.60@1692.92,1379.41
EXIT_10: P19.5 U1.63 | length 497.4
  Top Layer w10: P19.5@1560,962 1617.47,1019.47 1617.47,1079.62 1752.32,1214.47 U1.63@1752.32,1379.76
EXIT_11: P19.8 U1.64 | length 364.2
  Top Layer w10: P19.8@1660,1062 1772.01,1174.01 U1.64@1772.01,1379.76
EXIT_12: P19.7 U1.65 | length 472.3
  Top Layer w10: P19.7@1660,962 1717.47,1019.47 1717.47,1079.62 1791.69,1153.84 U1.65@1791.69,1379.76
EXIT_13: P19.10 U1.66 | length 339
  Top Layer w10: P19.10@1760,1062 1811.38,1113.38 U1.66@1811.38,1379.76
EXIT_14: P19.9 U1.67 | length 447.2
  Top Layer w10: P19.9@1760,962 1831.06,1033.06 U1.67@1831.06,1379.76
GLED_1: R34.2 U1.92 | length 2743.6
  Top Layer w10: U1.92@2007.24,1831.53 2066.13,1831.53 2080.66,1817 v1(2100,1817) v1(2730,1817)
  Top Layer w20: R34.2@2512,3422 2512,3405 v1(2540,3377)
  Bottom Layer w10: v1(2540,3377) 2545,3382 2854.14,3382 2860,3376.14 2860,2082 2885,2057 2885,1981.24 2730,1826.24 v1(2730,1817)
GLED_2: R35.2 U1.91 | length 963.9
  Top Layer w10: U1.91@2007.24,1811.84 2060.36,1811.84 2079.7,1792.5 v1(2180,1792.5) ; v1(2480,1717) 2746.98,1717 2870.17,1840.19 2871.98,1840.19 2876.98,1845.19 R35.2@2876.98,1847
  Bottom Layer w10: v1(2180,1792.5) 2329.5,1792.5 2405,1717 v1(2480,1717)
GLED_3: R36.2 U1.90 | length 1373.3
  Top Layer w10: U1.90@2007.24,1792.16 2054.59,1792.16 2082.75,1764 v1(2171,1764) ; v1(2715,920.5) R36.2@2756,920.5
  Bottom Layer w10: v1(2171,1764) 2174,1767 2314.14,1767 2335,1746.14 2335,1300.5 v1(2715,920.5)
GLED_4: R37.2 U1.89 | length 797.6
  Top Layer w10: R37.2@1858.68,1079.62 1859.34,1080.28 1859.34,1114.04 1858.68,1114.7 v1(1858.68,1257.58) ; v1(1925,1760.5) 1927.62,1760.5 1939.59,1772.47 U1.89@2007.24,1772.47
  Bottom Layer w10: v1(1858.68,1257.58) 1858.68,1695.68 v1@1925,1762
  other v1: 1860,1113.38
